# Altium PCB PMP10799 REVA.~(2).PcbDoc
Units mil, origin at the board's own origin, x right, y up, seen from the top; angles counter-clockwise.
Board outline 4950 x 3450 mil, 2 copper layers (Top Layer, Bottom Layer), stack 62 mil thick; 51 components, 27 nets, 127 pads, 4 vias.
Unrouted connection lines stored in the file: 92.
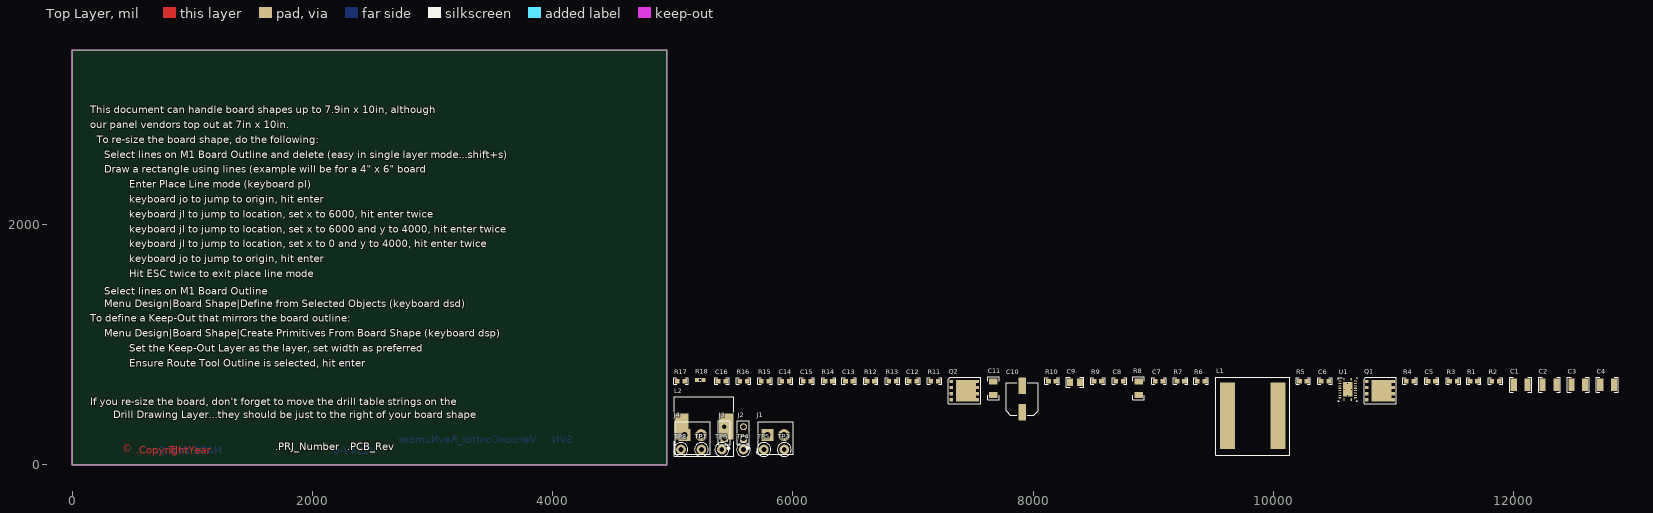
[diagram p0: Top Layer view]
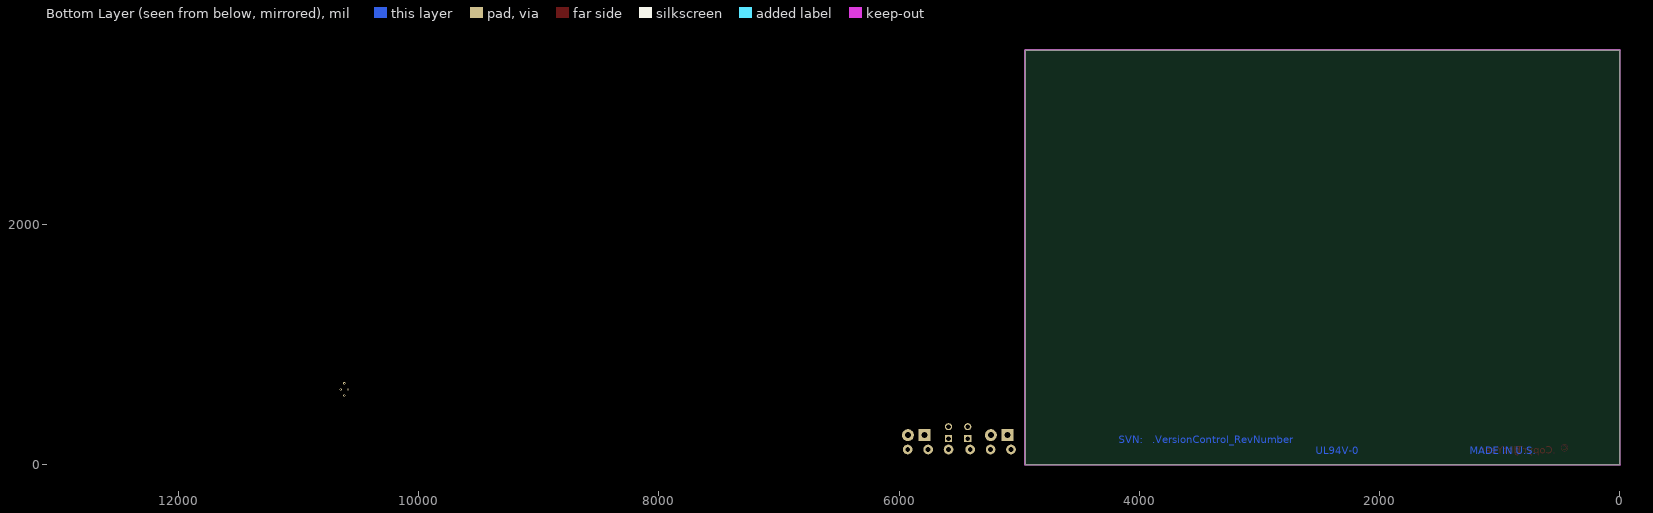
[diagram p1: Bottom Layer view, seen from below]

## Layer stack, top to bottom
Top Solder: solder mask 0.4, Solder Resist, Dk 3.5
Top Layer: signal copper 1.4
Dielectric1: core 59.2, FR-4, Dk 4.8
Bottom Layer: signal copper 1.4
Bottom Solder: solder mask 0.4, Solder Resist, Dk 3.5

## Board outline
0,0 4950,0 4950,3450 0,3450

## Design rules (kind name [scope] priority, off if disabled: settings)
AcuteAngle [All] p1: minimum=4.50000000000000E+0001 checktracksonly=FALSE
AssemblyTestPointUsage [All] p1: valid=2
Clearance Clearance_Keepouts [((IsTrack Or IsArc) And Not InPoly) And IsFree and IsKeepOut vs ((IsTrack Or IsArc) And Not InPoly) And IsFree and IsKeepOut] p1: gap=0
Clearance Clearance_BoardEdge_MountingHoles [OnCopper and InComponentClass('Mounting Holes') vs IsKeepOut] p2: gap=40
Clearance Clearance_BoardEdge_Poly [OnCopper and InPoly vs IsKeepOut] p3: gap=25
Clearance Clearance_BoardEdge [OnCopper and Not InComponentClass('Logo') and not InComponentClass('FiducialMark') and not InRegion(1000,500,4000,800) and Not IsKeepout vs IsKeepOut] p4: gap=75
Clearance Clearance_Poly [InPolygon] p5: gap=25
Clearance [All] p6: gap=7.87
ComponentClearance ComponentClearance_MountingHoles_FiducialMarks [InComponentClass('Mounting Holes') vs InComponentClass('FiducialMark')] p1: gap=50 collisioncheckmode=3 verticalgap=10 showdistances=FALSE
ComponentClearance ComponentClearance_Shunt [InComponentClass('Header') vs InComponentClass('Shunt')] p2: gap=0 collisioncheckmode=3 verticalgap=0 showdistances=FALSE
ComponentClearance ComponentClearance_Logo [InComponentClass('Logo')] p3: gap=50 collisioncheckmode=3 verticalgap=10 showdistances=FALSE
ComponentClearance ComponentClearance_ScrewToNut [(HasFootprint('NY PMS 440 0025 PH')) vs (HasFootprint('Keystone_1902C'))] p4: gap=5 collisioncheckmode=3 verticalgap=10 showdistances=FALSE
ComponentClearance ComponentClearance_MountingHoles [InComponentClass('Mounting Holes')] p5: gap=250 collisioncheckmode=3 verticalgap=100000 showdistances=FALSE
ComponentClearance ComponentClearance_SmallPassives [HasFootprint('0201*') or HasFootprint('0402*') or HasFootprint('0508') or HasFootprint('0603*') or HasFootprint('0612') or HasFootprint('0805*') or HasFootprint('0815*') or HasFootprint('0830*') or HasFootprint('1206*') or HasFootprint('1210*') or HasFootprint('1808*') or HasFootprint('1812*') or HasFootprint('1825*') or HasFootprint('2010*') or HasFootprint('2220*') or HasFootprint('2225*') or HasFootprint('2512*') or HasFootprint('2728*') or HasFootprint('3518*') vs HasFootprint('0201*') or HasFootprint('0402*') or HasFootprint('0508') or HasFootprint('0603*') or HasFootprint('0612') or HasFootprint('0805*') or HasFootprint('0815*') or HasFootprint('0830*') or HasFootprint('1206*') or HasFootprint('1210*') or HasFootprint('1808*') or HasFootprint('1812*') or HasFootprint('1825*') or HasFootprint('2010*') or HasFootprint('2220*') or HasFootprint('2225*') or HasFootprint('2512*') or HasFootprint('2728*') or HasFootprint('3518*')] p6: gap=20 collisioncheckmode=3 verticalgap=10 showdistances=FALSE
ComponentClearance ComponentClearance_THtoSMT [IsThruComponent vs IsSMTComponent] p7: gap=100 collisioncheckmode=3 verticalgap=30 showdistances=FALSE
ComponentClearance ComponentClearance_THtoTH [IsThruComponent vs IsThruComponent] p8: gap=118.11 collisioncheckmode=3 verticalgap=30 showdistances=FALSE
ComponentClearance [All] p9: gap=40 collisioncheckmode=3 verticalgap=10 showdistances=FALSE
DiffPairsRouting [All] p1: maxlimit=100 minlimit=10 mostfreqgap=10 toplayer_minwidth=15 toplayer_maxwidth=15 toplayer_prefwidth=15 bottomlayer_minwidth=15 bottomlayer_maxwidth=15 bottomlayer_prefwidth=15 maxuncoupledlength=1000
FabricationTestPointUsage TestPointUsage [All] p1: valid=2 allowmultiple=FALSE
FabricationTestpoint Testpoint [All] p1: side=3 testpointundercomponent=TRUE minsize=40 maxsize=100 preferedsize=60 minholesize=0 maxholesize=40 preferedholesize=32 testpointgrid=1 allowsidetop=TRUE allowsidebottom=TRUE usegrid=TRUE gridtolerance=0.01
FanoutControl Fanout_LCC [IsLCC] p1: bgadir=Out bgaviamode=Centered fanoutstyle=Auto fanoutdirection=Alternating viagrid=1 // Fanout_LCC (Default Rule)
FanoutControl Fanout_BGA [IsBGA] p2: bgadir=Out bgaviamode=Centered fanoutstyle=Auto fanoutdirection=Alternating viagrid=1 // Fanout_BGA (Default Rule)
FanoutControl Fanout_Default [All] p4: bgadir=Out bgaviamode=Centered fanoutstyle=Auto fanoutdirection=Alternating viagrid=1 // Fanout_Default (Default Rule)
FanoutControl Fanout_Small [(CompPinCount < 5)] p5: bgadir=Out bgaviamode=Centered fanoutstyle=Auto fanoutdirection=OutThenIn viagrid=1 // Fanout_Small (Default Rule)
HoleSize [All] p1: absolutevalues=TRUE maxlimit=251 minlimit=8 maxpercent=80.000 minpercent=20.000
MinimumAnnularRing MinimumAnnularRing_ThermalPadVias [IsVia and InAnyComponent] p1: minimumring=5.91
MinimumAnnularRing [All] p2: minimumring=9
MinimumSolderMaskSliver MinimumSolderMaskSliver_Logo [InComponentClass('Logo') vs InComponentClass('Logo')] p1: minsoldermaskwidth=0.7
MinimumSolderMaskSliver [All] p2: minsoldermaskwidth=3.94
PlaneConnect [All] p1: planeconnectstyle=Relief reliefexpansion=10 reliefentries=4 reliefconductorwidth=10 reliefairgap=10
PolygonConnect [All] p1: connectstyle=Relief reliefconductorwidth=10 reliefentries=4 polygonreliefangle="90 Angle" airgapwidth=10
RoutingVias ThermalPadVias [IsVia and InAnyComponent] p1: holewidth=7.87 width=19.68 viastyle="Through Hole" minholewidth=7.87 minwidth=19.68 maxholewidth=12.99 maxwidth=23.62
RoutingVias [All] p2: holewidth=16 width=34 viastyle="Through Hole" minholewidth=7.87 minwidth=26 maxholewidth=40 maxwidth=65
SilkToBoardRegionClearance [Not ((IsComment or IsDesignator) And (Hide <> 'False')) and not InRegion(1000,500,4000,800)] p1:
SilkToSilkClearance SilkToSilkClearance_Pb-FreeLogo [(HasFootprint('Pb-Free_Overlay_Medium') OR HasFootprint('Pb-Free_Overlay_Small')) vs (HasFootprint('Pb-Free_Overlay_Medium') OR HasFootprint('Pb-Free_Overlay_Small'))] p1: silktosilkclearance=0
SilkToSilkClearance [All] p2: silktosilkclearance=5
SilkToSolderMaskClearance "Silk to Solder Mask Opening" [All] p1: minsilkscreentomaskgap=1 clearancetoexposedcopper=FALSE
SolderMaskExpansion [All] p1: expansion=1.97
UnpouredPolygon [All] p1: allowunpoured=FALSE
Width [All] p1: maxlimit=100 minlimit=6 preferedwidth=10 checkconnectedcopper=TRUE
14 further rules are at their usual default settings.

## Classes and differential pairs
component class Header: J2 J3

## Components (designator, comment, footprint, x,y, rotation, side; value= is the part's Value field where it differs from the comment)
C1 "GRM32ER61H106MA12" 1210 12058,666 r0 top
C2 "GRM32ER61H106MA12" 1210 12298,666 r0 top
C3 "GRM32ER61H106MA12" 1210 12538,666 r0 top
C4 "GRM32ER61H106MA12" 1210 12778,666 r0 top
C5 "C1608X7R1H102K" 0603 11318,696 r0 top
C6 "C1608X7R1H104K" 0603 10428,696 r0 top
C7 "C1608C0G1H330J" 0603 9048,696 r0 top
C8 "C1608C0G1E472J" 0603 8718,696 r0 top
C9 "GRM21BR71C475KA73L" 0805_HV 8348,686 r0 top
C10 "16SVPF180M" SM_RADIAL_6.3AMM 7908,546 r90 top
C11 "GRM31CR71C106MAC7" 1206 7668,636 r90 top
C12 "C1608X7R1H102K" 0603 6998,696 r0 top
C13 "C1608X7R1H104K" 0603 6468,696 r0 top
C14 "C1608X7R1H333K" 0603 5938,696 r0 top
C15 "C1608X5R1C105K" 0603 6118,696 r0 top
C16 "C1608C0G1H152J" 0603 5408,696 r0 top
J1 "ED555/2DS" TERM_BLK_ED555-2DS 5788,246 r0 top
J2 "PEC02SAAN" CONN_PEC02SAAN 5588,266 r90 top
J3 "PEC02SAAN" CONN_PEC02SAAN 5428,266 r90 top
J4 "ED555/2DS" TERM_BLK_ED555-2DS 5098,246 r0 top
L1 "XAL1510" XAL1510 9828,406 r0 top
L2 "MSS1210-103ME" MSS1210 5258,316 r0 top
Q1 "CSD18503Q5A" TRANS_NexFET_Q5A 10888,616 r0 top
Q2 "CSD18503Q5A" TRANS_NexFET_Q5A 7428,616 r0 top
R1 "CRCW0603100KFKEA" 0603 11668,696 r0 top
R2 "CRCW0603301KFKEA" 0603 11848,696 r0 top
R3 "CRCW060315K0FKEA" 0603 11498,696 r0 top
R4 "CRCW060310K0FKEA" 0603 11138,696 r0 top
R5 "CRCW06034R70JNEA" 0603 10248,696 r0 top
R6 "CRCW06034R70JNEA" 0603 9398,696 r0 top
R7 "CRCW06034R70JNEA" 0603 9228,696 r0 top
R8 "ERJ-8RQF2R7V" 1206 8878,636 r90 top
R9 "CRCW060315K0FKEA" 0603 8538,696 r0 top
R10 "CRCW060310K0FKEA" 0603 8158,696 r0 top
R11 "CRCW060310K0FKEA" 0603 7178,696 r0 top
R12 "CRCW06037K87FKEA" 0603 6648,696 r0 top
R13 "" 0603 6828,696 r0 top
R14 "CRCW060331K6FKEA" 0603 6298,696 r0 top
R15 "CRCW06032K61FKEA" 0603 5768,696 r0 top
R16 "CRCW060349K9FKEA" 0603 5588,696 r0 top
R17 "CRCW06032K61FKEA" 0603 5068,696 r0 top
R18 "CRCW0603100RFKEA" 0603L 5228,706 r0 top
TP1 "5000" Keystone5000 5238,126 r0 top
TP2 "5001" Keystone5001 5068,126 r0 top
TP3 "5000" Keystone5000 5928,126 r0 top
TP4 "5000" Keystone5000 5588,126 r0 top
TP5 "5000" Keystone5000 5758,126 r0 top
TP6 "5001" Keystone5001 5408,126 r0 top
TP7 "5000" Keystone5000 5238,126 r0 top
TP8 "5000" Keystone5000 5068,126 r0 top
U1 "TPS40170RGY" RGY0020A 10618,626 r0 top

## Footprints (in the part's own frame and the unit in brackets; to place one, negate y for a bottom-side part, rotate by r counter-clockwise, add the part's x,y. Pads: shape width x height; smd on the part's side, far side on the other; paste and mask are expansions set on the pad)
0603 [mm] "0603 from SM-752 data"
  rect 1x0.95 smd: 1(-0.8,0) 2(0.8,0)
  silkscreen extent -1.52,-0.69 1.52,0.69, body extent -0.87,-0.47 0.87,0.47, height 0.85
0603L [mm] "0603 from SM-752 data"
  rect 0.8x0.85 smd: 1(-0.7,0) 2(0.7,0)
  silkscreen extent -0.07,-0.33 0.07,0.33, body extent -0.87,-0.47 0.87,0.47, height 0.85
0805_HV [mil] "0805 with 30mil clearance between pads"
  rect 50x63 smd: 1(-40,0) 2(40,0)
  silkscreen extent -74,-40 74,40, body extent -43,-29 43,29, height 43
1206 [mm] "1206 from SM-752 data"
  rect 1.3x1.85 smd: 1(-1.45,0) 2(1.45,0)
  silkscreen extent -2.4,-1.21 2.4,1.21, body extent -1.7,-0.9 1.7,0.9, height 1.35
1210 [mm] "1210 from SM-752 data"
  rect 1.3x2.7 smd: 1(-1.45,0) 2(1.45,0)
  silkscreen extent -2.32,-1.57 2.32,1.57, body extent -1.7,-1.35 1.7,1.35, height 1.35
CONN_PEC02SAAN [mm] "SULLINS"
  rect 1.5x1.5 hole 1.016: 1(-1.27,0)
  round 1.5 hole 1.016: 2(1.27,0)
  silkscreen extent -3.45,-1.27 2.54,1.27, body extent -2.54,-1.27 2.54,1.27, height 8.38
Keystone5000 [mil] "For Keystone 500x miniature loop terminals"
  round 80 hole 40: 1(0,0)
  silkscreen extent -58,-58 58,58, body extent -49,-49 49,49, height 182
Keystone5001 [mil] "For Keystone 500x miniature loop terminals"
  round 80 hole 40: 1(0,0)
  silkscreen extent -58,-58 58,58, body extent -49,-49 49,49, height 182
MSS1210 [mm] "Coilcraft MSS1210 series"
  rect 3x5.5 smd: 1(-4.75,0) 2(4.75,0)
  silkscreen extent -6.3,-6.3 6.3,6.3, body extent -6.15,-6.15 6.15,6.15, height 10.2
RGY0020A [mm] "QFN, 20-Leads, Body 4.5x3.5mm, Pitch 0.5mm, Thermal Pad 3.05x2.05mm, TI Recommended"
  oval 0.24x0.6 smd: 1(-0.75,2.15) 10(-0.75,-2.15) 11(0.75,-2.15) 20(0.75,2.15)
  oval 0.6x0.24 smd: 2(-1.65,1.75) 3(-1.65,1.25) 4(-1.65,0.75) 5(-1.65,0.25) 6(-1.65,-0.25) 7(-1.65,-0.75) 8(-1.65,-1.25) 9(-1.65,-1.75) 12(1.65,-1.75) 13(1.65,-1.25) 14(1.65,-0.75) 15(1.65,-0.25) 16(1.65,0.25) 17(1.65,0.75) 18(1.65,1.25) 19(1.65,1.75)
  rect 2.05x3.05 smd paste-1.025: 21(0,0)
  silkscreen extent -1.97,-2.47 1.97,2.47, body extent -1.83,-2.33 1.83,2.32, height 1.01
SM_RADIAL_6.3AMM [mm] "Nichicon 6.3x5.8"
  rect 3.5x1.6 smd: 1(-2.8,0) 2(2.8,0)
  silkscreen extent -3.4,-3.4 3.4,3.4, body extent -3.41,-3.41 3.41,3.41, height 6.1
TERM_BLK_ED555-2DS [mil]
  rect 100x100 hole 50: 1(0,0)
  round 100 hole 50: 2(138,0)
  silkscreen extent -93,-161 215,113, body extent -69,-150 207,106, height 323
TRANS_NexFET_Q5A [mm] "TI recommended land pattern (nominal) M0139-01"
  rect 0.75x0.675 smd paste-0.1 mask+0.051: 1(-2.776,1.917) 2(-2.776,0.639) 3(-2.776,-0.639) 4(-2.776,-1.917)
  rect 0.655x0.675 smd paste-0.1 mask+0.051: 5(2.776,-1.917) 6(2.776,-0.639) 7(2.776,0.639) 8(2.776,1.917)
  rect 4.295x4.51 smd paste-2.2 mask+0.051: 9(0.301,0)
  silkscreen extent -3.4,-2.8 3.4,2.8, body extent -3.05,-2.5 3.05,2.5, height 1.11
XAL1510 [mm] "COILCRAFT"
  rect 3.18x14.1 smd: 1(-5.3,0) 2(5.3,0)
  silkscreen extent -7.8,-8.3 7.8,8.2, body extent -7.7,-8.2 7.7,8.2, height 11

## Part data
C1 C2 C3 C4: library part C3225X7R1E106M, "CAP, CERM, 10uF, 50V, +/-20%, X5R, 1210"
C5 C12: "CAP, CERM, 1000 pF, 50 V, +/- 10%, X7R, 0603"
C6 C13: "CAP, CERM, 0.1uF, 50V, +/-10%, X7R, 0603"
C7: "CAP, CERM, 33 pF, 50 V, +/- 5%, C0G/NP0, 0603"
C8: "CAP, CERM, 4700 pF, 25 V, +/- 5%, C0G/NP0, 0603"
C9: "CAP, CERM, 4.7 µF, 16 V, +/- 10%, X7R, 0805"
C10: library part 16SVP39M, "CAP, OS-CON, 180 µF, 16 V, +/- 20%, 0.022 ohm, 6.3x5.9 SMD"
C11: library part GRM31CR71C106KAC7L, "CAP, CERM, 10 µF, 16 V, +/- 20%, X7R, 1206"
C14: library part C1608X7R1H473K, "CAP, CERM, 0.033 µF, 50 V, +/- 10%, X7R, 0603"
C15: "CAP, CERM, 1 µF, 16 V, +/- 10%, X5R, 0603"
C16: "CAP, CERM, 1500 pF, 50 V, +/- 5%, C0G/NP0, 0603"
J1 J4: "Terminal Block, 6A, 3.5mm Pitch, 2-Pos, TH"
J2 J3: "Header, 100mil, 2x1, Tin, TH"
L1: library part XAL1510-103MEB, "Inductor, open, SMD"
L2: "Inductor, Shielded, Ferrite, 10 µH, 10 A, 0.014 ohm, SMD"
Q1 Q2: library part CSD18501Q5A, "MOSFET, N-CH, 40 V, 3.4 milliohm, SON 5x6mm"
R1: "RES, 100 k, 1%, 0.1 W, 0603"
R2: "RES, 301 k, 1%, 0.1 W, 0603"
R3 R9: "RES, 15.0 k, 1%, 0.1 W, 0603"
R4 R10 R11: "RES, 10.0 k, 1%, 0.1 W, 0603"
R5 R6 R7: "RES, 4.7, 5%, 0.1 W, 0603"
R8: "RES, 2.70, 1%, 0.25 W, 1206"
R12: "RES, 7.87 k, 1%, 0.1 W, 0603"
R13: library part CRCW06037K87FKEA, "RES, open, 0603"
R14: "RES, 31.6 k, 1%, 0.1 W, 0603"
R15 R17: "RES, 2.61 k, 1%, 0.1 W, 0603"
R16: "RES, 49.9 k, 1%, 0.1 W, 0603"
R18: "RES, 100, 1%, 0.1 W, 0603"
TP1 TP3 TP4 TP5 TP7 TP8: "Test Point, Miniature, Red, TH"
TP2 TP6: "Test Point, Miniature, Black, TH"
U1: "4.5-v to 60-v wide-input synchronous PWM buck controller, RGY0020A"

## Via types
v1: diameter 19.68, hole 7.87, Top Layer to Bottom Layer, 4 vias

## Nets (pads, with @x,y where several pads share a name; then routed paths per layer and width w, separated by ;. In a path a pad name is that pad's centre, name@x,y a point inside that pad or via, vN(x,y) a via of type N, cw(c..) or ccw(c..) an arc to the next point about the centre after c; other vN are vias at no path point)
GND: C1.1 C2.1 C3.1 C4.1 C5.2 C9.2 C10.2 C11.2 C12.2 C13.1 C14.2 C15.2 J1.2 J2.2 J4.1 Q2.1 Q2.2 Q2.3 R3.1 R4.2 R12.1 R13.1 R14.1 R15.2 TP2.1 TP6.1 U1.9 U1.13 U1.21
  other v1: 10618,575.8 10587.49,626 10648.51,626 10618,676.2
NetC1_2: C1.2 C2.2 C3.2 C4.2 C13.2 J1.1 J3.2 Q1.5 Q1.6 Q1.7 Q1.8 Q1.9 R1.1 R2.2 TP1.1 U1.19
NetC5_1: C5.1 R2.1 R3.2 U1.20
NetC6_1: C6.1 L1.1 L2.1 Q1.1 Q1.2 Q1.3 Q2.5 Q2.6 Q2.7 Q2.8 Q2.9 R8.2 TP4.1 U1.16
NetC6_2: C6.2 R5.1
NetC7_1: C7.1 R9.2 R15.1 R16.2 R17.2 U1.7
NetC7_2: C7.2 C8.2 U1.8
NetC8_1: C8.1 R9.1
NetC9_1: C9.1 U1.15
NetC10_1: C10.1 C11.1 J4.2 L1.2 L2.2 R18.2 TP5.1
NetC12_1: C12.1 R8.1
NetC14_1: C14.1 U1.5
NetC15_1: C15.1 R10.2 R11.2 U1.10
NetC16_1: C16.1 R17.1
NetC16_2: C16.2 R16.1 R18.1 TP8.1
NetJ2_1: J2.1 R1.2 R4.1 U1.1
NetJ3_1: J3.1 U1.3
NetQ1_4: Q1.4 R6.1
NetQ2_4: Q2.4 R7.1
NetR5_2: R5.2 U1.18
NetR6_2: R6.2 U1.17
NetR7_2: R7.2 R13.2 U1.14
NetR10_1: R10.1 U1.6
NetR11_1: R11.1 TP7.1 U1.11
NetR12_2: R12.2 U1.12
NetR14_2: R14.2 U1.4
NetTP3_1: TP3.1 U1.2

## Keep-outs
Keep-Out Layer:
  lines w10: -5,0 ccw(c0,0) 0,-5 ; -5,0 ccw(c0,0) 0,-5 ; -5,0 -5,3450 ; -5,3450 cw(c0,3450) 0,3455 ; -5,3450 cw(c0,3450) 0,3455 ; 0,-5 4950,-5 ; 0,3455 4950,3455 ; 4950,-5 ccw(c4950,0) 4955,0 ; 4950,-5 ccw(c4950,0) 4955,0 ; 4950,3455 cw(c4950,3450) 4955,3450 ; 4950,3455 cw(c4950,3450) 4955,3450 ; 4955,0 4955,3450
  text ".Layer_Name" at 577,-858.49 h60

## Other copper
Top Layer:
  text ".CopyrightYear" at 532,90 h60
  text "TI" at 808,90 h60
  text "©" at 415,86.48 h105
  text ".Layer_Name" at 577,-858.49 h60
Bottom Layer:
  text ".VersionControl_RevNumber" at 3891,179.5 h60
  text "SVN:" at 4170,179.5 h60
  text "MADE IN U.S." at 1250,86.5 h60
  text "UL94V-0" at 2529.5,86.5 h60
  text ".Layer_Name" at 577,-858.49 h60

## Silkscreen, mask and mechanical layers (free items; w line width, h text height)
Top Overlay:
  text "This document can handle board shapes up to 7.9in x 10in, although" at 150,2925 h60
  text "our panel vendors top out at 7in x 10in." at 150,2800.94 h60
  text "To re-size the board shape, do the following:" at 205,2676.88 h60
  text "Select lines on M1 Board Outline and delete (easy in single layer mode...shift+s)" at 265,2552.82 h60
  text "Draw a rectangle using lines (example will be for a 4\" x 6\" board" at 265,2428.76 h60
  text "Enter Place Line mode (keyboard pl)" at 475,2304.71 h60
  text "keyboard jo to jump to origin, hit enter" at 475,2180.65 h60
  text "keyboard jl to jump to location, set x to 6000, hit enter twice" at 475,2056.59 h60
  text "keyboard jl to jump to location, set x to 6000 and y to 4000, hit enter twice" at 475,1932.53 h60
  text "keyboard jl to jump to location, set x to 0 and y to 4000, hit enter twice" at 475,1808.47 h60
  text "keyboard jo to jump to origin, hit enter" at 475,1684.41 h60
  text "Hit ESC twice to exit place line mode" at 475,1560.35 h60
  text "Select lines on M1 Board Outline" at 265,1416.3 h60
  text "Menu Design|Board Shape|Define from Selected Objects (keyboard dsd)" at 265,1312.24 h60
  text "To define a Keep-Out that mirrors the board outline:" at 150,1188.18 h60
  text "Menu Design|Board Shape|Create Primitives From Board Shape (keyboard dsp)" at 265,1064.12 h60
  text "Set the Keep-Out Layer as the layer, set width as preferred" at 475,940.06 h60
  text "Ensure Route Tool Outline is selected, hit enter" at 475,816 h60
  text "If you re-size the board, don't forget to move the drill table strings on the" at 150,493 h60
  text "Drill Drawing Layer...they should be just to the right of your board shape" at 343,387 h60
  text ".PRJ_Number" at 1690,120 h60
  text ".PCB_Rev" at 2290,120 h60
  text ".Layer_Name" at 577,-858.49 h60
Bottom Overlay:
  text ".Layer_Name" at 577,-858.49 h60
Top Paste:
  text ".Layer_Name" at 577,-858.49 h60
Bottom Paste:
  text ".Layer_Name" at 577,-858.49 h60
Top Solder:
  text ".Layer_Name" at 577,-858.49 h60
  text ".Layer_Name" at 577,-858.49 h60
Bottom Solder:
  text ".Layer_Name" at 577,-858.49 h60
Drill Guide:
  text ".Layer_Name" at 577,-858.49 h60
M1 Board Outline:
  the board outline again, w10
  text ".Layer_Name" at 577,-858.49 h60
M2 Board Dimensions:
  rectangle: 0,-275 125,-150
  rectangle: 125,-400 500,-275
  lines w7: 0,-275 1000,-275 ; 125,-400 125,-150 ; 250,-400 250,-150 ; 500,-400 500,-150 ; 750,-400 750,-150 ; 0,-400 1000,-400 1000,-150 0,-150 0,-400
  text ".Layer_Name" at 577,-858.49 h60
M3 3D STEP Top:
  text ".Layer_Name" at 577,-858.49 h60
M4 3D STEP Bottom:
  text ".Layer_Name" at 577,-858.49 h60
M5 Assembly Top:
  lines w10: -292,-930.17 6308,-930.17 ; -292,-726.83 6310,-726.83 ; -292,-523.5 -292,-1133.5 3713,-1133.5 6310,-1133.5 6310,-523.5 -291.5,-523.5 -291.5,-1133.5 1284,-1133.5 ; 2173,-1133.5 2173,-523.5 ; 3440,-726.83 3440,-523.5 ; 4280,-726.83 4280,-523.5 ; 4902,-1140 4902,-937.17
  text "COMPONENTS MARKED 'DNP' SHOULD NOT BE POPULATED." at 1153.5,-318.5 h60
  text "ASSEMBLY VARIANT:" at 1153,-434 h60
  text ".VariantName" at 2189,-434 h60
  text "PCB VIEWED FROM TOP SIDE" at -228.5,-655.67 h60
  text "BOARD #:" at 2248,-655.67 h60
  text ".PRJ_Number" at 2793.5,-655.67 h60
  text "REV:" at 3638,-655.67 h60
  text ".PCB_Rev" at 3929.5,-655.67 h60
  text "SVN REV:" at 4476,-655.67 h60
  text ".VersionControl_RevNumber" at 4982,-655.67 h60
  text "PLOT NAME =" at -228.5,-1064.34 h60
  text ".plot_File_Name" at 577,-1064.34 h60
  text "GENERATED    :" at 2250,-1064.34 h60
  text ".Print_Date" at 3119.5,-1064.34 h60
  text ".Print_Time" at 3848.5,-1064.34 h60
  text "TEXAS INSTRUMENTS" at 5113,-1064.34 h60
M6 Assembly Bottom:
  lines w10: -292.5,-727.33 6309.5,-727.33 ; -290.5,-930.67 6309.5,-930.67 ; 1115.5,-1140.5 1115.5,-937.67 ; 1737.5,-727.33 1737.5,-524 ; 2577.5,-727.33 2577.5,-524 ; 3844.5,-1134 3844.5,-524 ; 4733.5,-1134 6309,-1134 6309,-524 -292.5,-524 -292.5,-1134 2304.5,-1134 6309.5,-1134 6309.5,-524
  text "COMPONENTS MARKED 'DNP' SHOULD NOT BE POPULATED." at 6102,-318 h60
  text ".VariantName" at 5058,-434 h60
  text "ASSEMBLY VARIANT:" at 6097,-434 h60
  text ".VersionControl_RevNumber" at 1035.5,-656.17 h60
  text "SVN REV:" at 1541.5,-656.17 h60
  text ".PCB_Rev" at 2088,-656.17 h60
  text "REV:" at 2379.5,-656.17 h60
  text ".PRJ_Number" at 3224,-656.17 h60
  text "BOARD #:" at 3769.5,-656.17 h60
  text "PCB VIEWED FROM BOTTOM SIDE" at 6246,-656.17 h60
  text "TEXAS INSTRUMENTS" at 904.5,-1064.84 h60
  text ".Print_Time" at 2169,-1064.84 h60
  text ".Print_Date" at 2898,-1064.84 h60
  text "GENERATED    :" at 3767.5,-1064.84 h60
  text ".plot_File_Name" at 5440.5,-1064.84 h60
  text "PLOT NAME =" at 6246,-1064.84 h60
M9 Title Sheet:
  drawing of 57 lines, arcs and shapes, not listed
  text "1" at 739.84,8036.5 h70
  text "2" at 3235.5,8036.5 h70
  text "3" at 5724.84,8036.5 h70
  text "4" at 8231.51,8036.5 h70
  text "5" at 10730.5,8036.5 h70
  text "6" at 13235.5,8036.5 h70
  text "A" at -416.5,6893.5 h70
  text "A" at 14383.5,6893.5 h70
  text "B" at -416.5,4513.5 h70
  text "B" at 14383.5,4513.5 h70
  text "C" at -416.5,2138.5 h70
  text "C" at 14383.5,2138.5 h70
  text "PROJECT TITLE:" at 11343.5,277.5 h45
  text ".PRJ_Title" at 11393.5,144.17 h70
  text "DESIGNED FOR:" at 11343.5,-23.5 h45
  text ".PRJ_Customer" at 11393.5,-163.5 h70
  text "D" at -416.5,-231.5 h70
  text "D" at 14383.5,-231.5 h70
  text "FILE NAME:" at 11343.5,-323.5 h45
  text ".PCB_File_Name_No_Path" at 11393.5,-443.5 h70
  text "Texas Instruments (TI) and/or its licensors do not warrant the accuracy or completeness of this specification" at 6374,-605.34 h45
  text "ENGINEER:" at 11343.5,-613.5 h45
  text "LAYOUT BY:" at 12848.5,-613.5 h45
  text "or any information contained therein. TI and/or its licensors do not warrant that this design will meet" at 6329.01,-718 h45
  text ".PRJ_Engineer" at 11393.5,-768.49 h70
  text ".PCB_Layout" at 12899,-768.49 h70
  text "the specifications, will be suitable for your application or fit for any particular purpose, or will operate in" at 6329.01,-830.67 h45
  text ".Layer_Name" at 577,-858.49 h60
  text "ALTIUM DESIGNER VERSION:" at 12848.5,-923.5 h45
  text "an implementation. TI and/or its licensors do not warrant that the design is production worthy. You should" at 6329.01,-943.33 h45
  text "completely validate and test your design implementation to confirm the system functionality for your application." at 6374,-1056 h45
  text ".print_Scale" at 11393.5,-1056.83 h70
  text ".Application_BuildNumber" at 12899,-1056.83 h70
  text "1" at 739.84,-1263.5 h70
  text "2" at 3235.5,-1263.5 h70
  text "3" at 5724.84,-1263.5 h70
  text "4" at 8231.51,-1263.5 h70
  text "5" at 10730.5,-1263.5 h70
  text "6" at 13235.5,-1263.5 h70
M10 Fab Notes:
  drawing of 185 lines, arcs and shapes, not listed
  text "DESIGN INFORMATION" at 12381.02,5910 h60
  text "MIN. TRACK WIDTH:" at 11736.46,5730 h60
  text "8" at 12832.7,5730 h60
  text "MIL" at 12987.46,5730 h60
  text "MIN. CLEARANCE:" at 11736.46,5598 h60
  text "0.2" at 12772.7,5598 h60
  text "mm" at 12987.46,5598 h60
  text "MIN. VIA PAD SIZE:" at 11736.46,5466 h60
  text "24" at 12802.71,5466 h60
  text "MIL" at 12987.46,5466 h60
  text "0.05mm (2MIL)" at 12431.46,5324.29 h60
  text "MINIMUM ANNULAR RING" at 11407.23,5320 h60
  text "EXTERNAL" at 13139.46,5320 h60
  text "PER" at 11607.23,5202 h60
  text "IPC-D-275 CLASS 2 LEVEL C" at 11827.23,5202 h60
  text "MIL, HOLES" at 13315.46,5089.71 h60
  text "+/-" at 12923,5089 h60
  text "+/-" at 13777,5089 h60
  text "REGISTRATION TOLERANCES:" at 11407.23,5084 h60
  text "METAL" at 12607,5084 h60
  text "5" at 13183.2,5084 h60
  text "3" at 14016.2,5084 h60
  text "MIL" at 14132.46,5084 h60
  text "MATERIAL:" at 11332.46,4874.54 h60
  text "FR-4 High Tg" at 12318.9,4734.21 h60
  text "FR-408" at 11753.46,4725.64 h60
  text "X" at 12165.46,4725.64 h60
  text "OTHER" at 13241.46,4725.64 h60
  text "62 MIL (1.6mm) +/-10%" at 12073.56,4562.92 h60
  text "THICKNESS:" at 11407.23,4558.64 h60
  text "X" at 11945.4,4558.64 h60
  text "OTHER" at 13358.46,4558.64 h60
  text "TOLERANCE:" at 11407.23,4400.64 h60
  text "X" at 12246.53,4400.64 h60
  text "ANSI IPC-6012 TYPE 3 CLASS 2" at 12433.48,4400.64 h60
  text "OTHER +/-" at 12433.46,4244.64 h60
  text "BOW & TWIST:" at 11407.23,4087.64 h60
  text "X" at 12246.53,4087.64 h60
  text "ANSI IPC-6012 TYPE 3 CLASS 2" at 12433.48,4087.64 h60
  text "OTHER +/-" at 12433.46,3929.13 h60
  text "DRILLING:" at 11332.46,3790.64 h60
  text "REFERENCE:" at 11407.23,3673.64 h60
  text "X" at 12055.46,3673.64 h60
  text "AS SHOWN" at 12242.46,3673.64 h60
  text "X" at 12956.46,3673.64 h60
  text "NC_DRILL FILES" at 13093.46,3673.64 h60
  text "PTH MIN COPPER THICKNESS:" at 11407.23,3515.64 h60
  text "X" at 12757.46,3515.64 h60
  text "1MIL" at 12894.46,3515.64 h60
  text "OTHER" at 13391.46,3515.64 h60
  text "BOARD FINISH:" at 11332.46,3356.64 h60
  text "SILKSCREEN:" at 11487.68,3238.64 h60
  text "X" at 12436.46,3238.64 h60
  text "TOP" at 12562.46,3238.64 h60
  text "X" at 12946.46,3238.64 h60
  text "BOTTOM" at 13073.46,3238.64 h60
  text "SILKSCREEN COLOR:" at 11487.68,3071.64 h60
  text "X" at 12435.42,3071.64 h60
  text "WHITE" at 12562.46,3071.64 h60
  text "OTHER" at 13073.46,3071.64 h60
  text "SOLDER RESIST COLOR:" at 11487.68,2901.64 h60
  text "X" at 12055.42,2742.44 h60
  text "GREEN" at 12182.46,2742.44 h60
  text "BLUE" at 12773.46,2742.44 h60
  text "OTHER" at 13311.46,2742.44 h60
  text "IMMERSION GOLD (ENIG)" at 12393.46,2553.92 h60
  text "ENEPIG" at 13731,2550.64 h60
  text "SURFACE FINISH:" at 11332.46,2549.64 h60
  text "X" at 12206.51,2549.64 h60
  text "IMM. TIN/SILVER OR EQUIV" at 11662,2392.64 h60
  text "OTHER" at 13093.46,2392.64 h60
  text "ARRAY/PANEL:" at 11332.46,2213.64 h60
  text "CUT AND TRIM PER MECH LAYER 1" at 12393.46,2209.35 h60
  text "N.C. ROUTE" at 12393.46,2057.64 h60
  text "X" at 13072.46,2057.64 h60
  text "V. SCORE" at 13259.46,2057.64 h60
  text "CERTIFICATION:" at 11332.46,1920.64 h60
  text "MATERIALS AND WORKMANSHIP FOR ALL PCBS" at 12057.46,1920.64 h60
  text "TO MEET OR EXCEED THE REQUIREMENTS OF:" at 12057.46,1822.64 h60
  text "X" at 11683.96,1686.13 h60
  text "ANSI IPC-A-600F CLASS ->" at 11822.96,1686.13 h60
  text "X" at 13462.02,1686.13 h60
  text "2" at 13580.96,1686.14 h60
  text "1" at 13265.96,1684.64 h60
  text "3" at 13934.96,1684.64 h60
  text "X" at 11686.02,1526.64 h60
  text "UL 94V-0" at 11822.96,1526.64 h60
  text "X" at 12498.02,1526.64 h60
  text "RoHS" at 12634.96,1526.64 h60
  text "OTHER" at 13279.36,1526.64 h60
  text "PER ORDER" at 13676.42,1526.64 h60
  text "ADDITIONAL REQUIREMENTS:" at 11332.46,1385.64 h60
  text "MICROSECTION:" at 11407.23,1270.64 h60
  text "YES" at 12312.96,1270.64 h60
  text "REQUIRED" at 13174.46,1114.49 h60
  text "BARE BOARD ELEC. TEST:" at 11407.23,1111.64 h60
  text "NONE" at 12712.96,1111.64 h60
  text "X" at 13047.46,1111.64 h60
  text "PER ORDER" at 13766.46,1111.64 h60
  text "MANUFACTURER'S UL:" at 11407.23,954.64 h60
  text "RAIL" at 12572.96,950.35 h60
  text "METAL" at 13064.77,950.35 h60
  text "X" at 13440,950 h60
  text "SILK" at 13576.46,950.35 h60
  text ".Layer_Name" at 577,-858.49 h60
M11 Gerber Information:
  lines w10: -292,-930.17 6308,-930.17 ; -292,-726.83 6310,-726.83 ; -292,-523.5 -292,-1133.5 3713,-1133.5 6310,-1133.5 6310,-523.5 -291.5,-523.5 -291.5,-1133.5 1284,-1133.5 ; 2173,-1133.5 2173,-523.5 ; 3440,-726.83 3440,-523.5 ; 4280,-726.83 4280,-523.5 ; 4902,-1140 4902,-937.17
  text "ALL ARTWORK VIEWED FROM TOP SIDE" at -228.5,-655.67 h60
  text "BOARD #:" at 2248,-655.67 h60
  text ".PRJ_Number" at 2793.5,-655.67 h60
  text "REV:" at 3638,-655.67 h60
  text ".PCB_Rev" at 3929.5,-655.67 h60
  text "SVN REV:" at 4476,-655.67 h60
  text ".VersionControl_RevNumber" at 4982,-655.67 h60
  text "LAYER NAME =" at -228.5,-858.49 h60
  text "PLOT NAME =" at -228.5,-1064.34 h60
  text ".plot_File_Name" at 577,-1064.34 h60
  text "GENERATED    :" at 2250,-1064.34 h60
  text ".Print_Date" at 3119.5,-1064.34 h60
  text ".Print_Time" at 3848.5,-1064.34 h60
  text "TEXAS INSTRUMENTS" at 5113,-1064.34 h60
M12 Stackup:
  drawing of 191 lines, arcs and shapes, not listed
  text "Layer" at 9790.58,7830 h60
  text "Name" at 10200.49,7830 h60
  text "Material" at 11130.23,7830 h60
  text "Thickness" at 11990,7830 h60
  text "Constant" at 12639.84,7830 h60
  text "Board Layer Stack" at 13209.7,7830 h60
  text "1" at 9790.58,7710 h60
  text "Top Overlay" at 10200.49,7710 h60
  text "2" at 9790.58,7590 h60
  text "Top Solder" at 10200.49,7590 h60
  text "Solder Resist" at 11130.23,7590 h60
  text "0.40mil" at 11990,7590 h60
  text "3.5" at 12639.84,7590 h60
  text "3" at 9790.58,7470 h60
  text "Top Layer" at 10200.49,7470 h60
  text "Copper" at 11130.23,7470 h60
  text "1.40mil" at 11990,7470 h60
  text "4" at 9790.58,7350 h60
  text "Dielectric1" at 10200.49,7350 h60
  text "FR-4" at 11130.23,7350 h60
  text "59.20mil" at 11990,7350 h60
  text "4.8" at 12639.84,7350 h60
  text "5" at 9790.58,7230 h60
  text "Bottom Layer" at 10200.49,7230 h60
  text "Copper" at 11130.23,7230 h60
  text "1.40mil" at 11990,7230 h60
  text "6" at 9790.58,7110 h60
  text "Bottom Solder" at 10200.49,7110 h60
  text "Solder Resist" at 11130.23,7110 h60
  text "0.40mil" at 11990,7110 h60
  text "3.5" at 12639.84,7110 h60
  text "7" at 9790.58,6990 h60
  text "Bottom Overlay" at 10200.49,6990 h60
  text ".Layer_Name" at 577,-858.49 h60
M13 Component Bodies Top:
  text ".Layer_Name" at 577,-858.49 h60
M14 Component Bodies Bottom:
  text ".Layer_Name" at 577,-858.49 h60
M15 Courtyards Top:
  text ".Layer_Name" at 577,-858.49 h60
M16 Courtyards Bottom:
  text ".Layer_Name" at 577,-858.49 h60
Drill Drawing:
  circle w1: c5572.72,3221.04 r24.89
  lines w1: 5547.83,2947.29 5597.6,2947.29 5572.72,2897.52 5547.83,2947.29 ; 5547.83,3046.84 5597.6,3046.84 5597.6,3096.61 5547.83,3096.61 5547.83,3046.84
  lines w12: 5480,2852.72 7598.02,2852.72 ; 5480,3300.68 7598.02,3300.68 ; 5850.36,2703.4 5850.36,3450 ; 6207.36,2703.4 6207.36,3450 ; 6868.93,2703.4 6868.93,3450 ; 7153.07,2703.4 7153.07,3450 ; 5480,2703.4 7598.02,2703.4 7598.02,3450 5480,3450 5480,2703.4
  text "Symbol" at 5569.59,3345.48 h72
  text "Quantity" at 5895.16,3345.48 h72
  text "Finished Hole Size" at 6252.16,3345.48 h72
  text "Plated" at 6913.72,3345.48 h72
  text "Hole Type" at 7197.86,3345.48 h72
  text "4" at 5895.16,3196.16 h60
  text "7.87mil (0.200mm)" at 6252.16,3196.16 h60
  text "PTH" at 6913.72,3196.16 h60
  text "Round" at 7197.86,3196.16 h60
  text "12" at 5895.16,3046.84 h60
  text "40.00mil (1.016mm)" at 6252.16,3046.84 h60
  text "PTH" at 6913.72,3046.84 h60
  text "Round" at 7197.86,3046.84 h60
  text "4" at 5895.16,2897.52 h60
  text "50.00mil (1.270mm)" at 6252.16,2897.52 h60
  text "PTH" at 6913.72,2897.52 h60
  text "Round" at 7197.86,2897.52 h60
  text "20 Total" at 5895.16,2748.2 h60
  text ".Layer_Name" at 577,-858.49 h60

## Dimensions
0,-400 to 1000,-400 on M2 Board Dimensions
0,0 to 0,3450 on M2 Board Dimensions
0,0 to 4950,0 on M2 Board Dimensions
